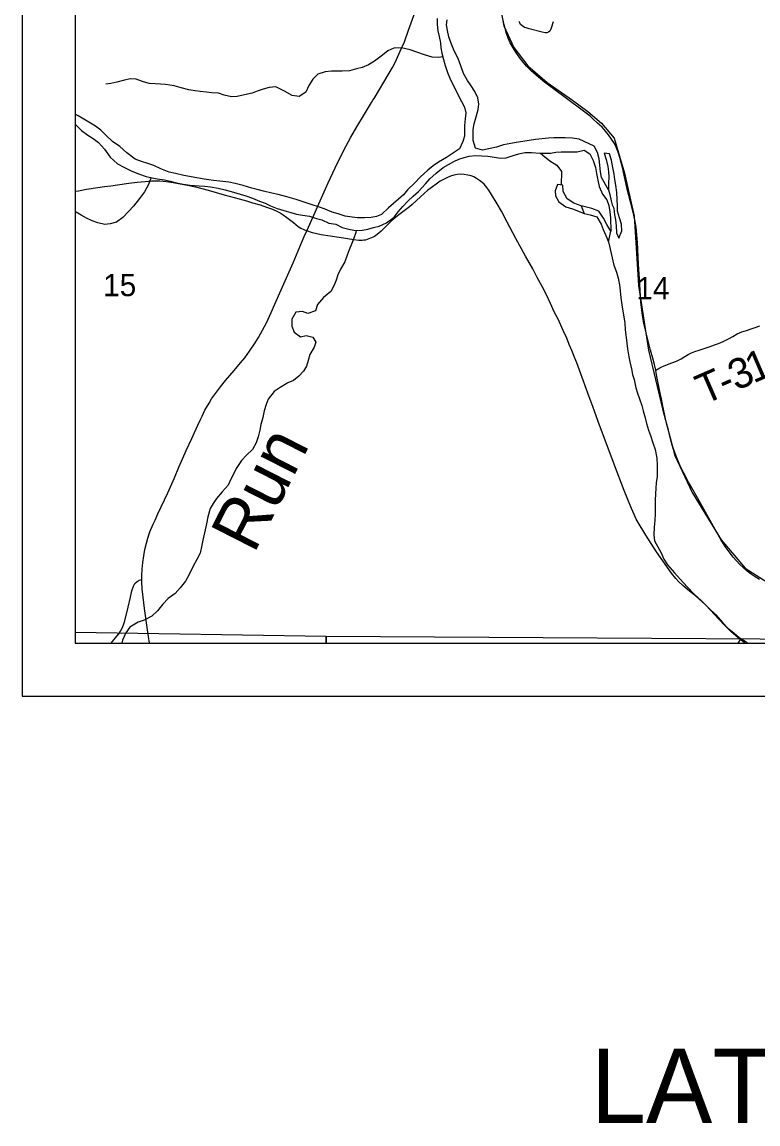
# Model space of a CAD drawing. Extents: x -7.5 to 53.5, y 0 to 22.
# Drawn here: x 2 to 3.386, y 13.194 to 15.27 of the extents above; entities that cross this region are included whole.
import ezdxf

# ---------------------------------------------------------------- set-up
doc = ezdxf.new("R2010")
doc.units = 0
for name, color, linetype in [('GM_X_Corporation', 7, 'Continuous'), ('GM_X_County_Road', 7, 'Continuous'), ('GM_X_Major_River', 7, 'Continuous'), ('GM_X_Minor_River', 7, 'Continuous'), ('GM_X_Minor_River_Text', 7, 'Continuous'), ('GM_X_Rail_Line', 7, 'Continuous'), ('GM_X_Section_Text', 7, 'Continuous'), ('GM_X_State_Route', 7, 'Continuous'), ('GM_X_Township_Road', 7, 'Continuous'), ('GM_X_Township_Road_Text', 7, 'Continuous'), ('SH_Data', 7, 'Continuous'), ('SH_Text', 7, 'Continuous')]:
    doc.layers.add(name, color=color, linetype=linetype)

msp = doc.modelspace()

# ---------------------------------------------------------------- linework, layer by layer
at = {"layer": 'GM_X_Corporation'}
msp.add_lwpolyline([(2.1, 20.9), (2.1, 14.1), (4.6151, 14.1), (4.6149, 14.11), (4.6147, 14.1199), (4.6087, 14.5302), (4.6021, 15.6139)], dxfattribs=at)
for points in [[(2.1, 14.1198), (2.1, 14.1), (2.573, 14.1), (2.573, 14.1127)], [(2.573, 14.1), (3.5941, 14.1), (3.594, 14.1064), (2.573, 14.1127)]]:
    msp.add_lwpolyline(points, close=True, dxfattribs=at)
at = {"layer": 'GM_X_County_Road'}
for points in [[(3.1934, 14.6146), (3.193, 14.6166), (3.1909, 14.6251), (3.188, 14.6371), (3.1839, 14.6522), (3.176, 14.6822), (3.1712, 14.7023), (3.1683, 14.7182), (3.1671, 14.7275), (3.1655, 14.7428), (3.1627, 14.7864), (3.161, 14.814), (3.159, 14.8549), (3.158, 14.8693), (3.1565, 14.8835), (3.154, 14.8976), (3.151, 14.9123), (3.1457, 14.9318), (3.1402, 14.9529), (3.1345, 14.9788), (3.1309, 14.9959), (3.1261, 15.0151), (3.1228, 15.0248), (3.1189, 15.0343), (3.1156, 15.0413), (3.1103, 15.0497), (3.1046, 15.0578), (3.0991, 15.0648), (3.0925, 15.072), (3.0841, 15.08), (3.0757, 15.0875), (3.0697, 15.0928), (3.06, 15.1004), (3.0228, 15.1282), (2.9842, 15.1568), (2.9724, 15.1664), (2.9595, 15.1778), (2.9502, 15.1873), (2.9435, 15.1948), (2.9368, 15.2034), (2.9297, 15.2138), (2.9252, 15.2214), (2.9196, 15.2314), (2.9156, 15.2399), (2.9125, 15.2486), (2.9096, 15.2578), (2.9078, 15.2652), (2.9062, 15.2737)], [(3.3889, 14.2198), (3.381, 14.2248), (3.3733, 14.23), (3.3658, 14.2357), (3.3587, 14.2418), (3.3518, 14.2482), (3.3453, 14.2549), (3.3392, 14.262), (3.3335, 14.2694), (3.3245, 14.2822), (3.3163, 14.2954), (3.3054, 14.3142), (3.284, 14.3521), (3.2719, 14.3738), (3.2612, 14.3927), (3.255, 14.4033), (3.2462, 14.42), (3.2395, 14.4339), (3.2342, 14.4459), (3.2299, 14.4573), (3.2247, 14.4729), (3.22, 14.4901), (3.2172, 14.5012), (3.2128, 14.5193), (3.21, 14.5322), (3.207, 14.5465), (3.2042, 14.5601), (3.2014, 14.5742), (3.1963, 14.5991), (3.1945, 14.609), (3.1934, 14.6146)], [(2.1762, 14.1097), (2.1788, 14.1128), (2.1825, 14.1176), (2.1857, 14.1228), (2.1887, 14.1282), (2.1913, 14.1344), (2.1935, 14.1417), (2.1999, 14.1679), (2.2041, 14.1864), (2.207, 14.1984), (2.2098, 14.2071), (2.2127, 14.2122), (2.2168, 14.2161), (2.2206, 14.2183), (2.2256, 14.22)], [(2.1678, 14.1), (2.173, 14.106), (2.1762, 14.1097)]]:
    msp.add_lwpolyline(points, dxfattribs=at)
at = {"layer": 'GM_X_Major_River'}
msp.add_line((3.0531, 14.9242), (3.0588, 14.9098), dxfattribs=at)
for points in [[(2.7817, 15.2772), (2.7817, 15.2655), (2.7832, 15.2537), (2.7855, 15.2431), (2.7878, 15.231), (2.7889, 15.2215), (2.7908, 15.2116), (2.7939, 15.1995), (2.7966, 15.1885), (2.8011, 15.1753), (2.8057, 15.1643), (2.8118, 15.1514), (2.8277, 15.1207), (2.8334, 15.1097), (2.8357, 15.0995), (2.8346, 15.0881), (2.8331, 15.0752), (2.8335, 15.065), (2.8331, 15.0551), (2.8304, 15.0449), (2.8236, 15.0312), (2.8127, 15.0236), (2.7994, 15.0149), (2.7842, 15.0065), (2.7744, 14.9993), (2.7642, 14.9909), (2.7498, 14.978), (2.7399, 14.967), (2.7259, 14.9541), (2.7183, 14.9446), (2.6903, 14.9203), (2.6771, 14.9078), (2.6676, 14.9036), (2.6574, 14.9017), (2.6448, 14.9013), (2.6316, 14.9016), (2.6217, 14.9024), (2.6085, 14.9043), (2.5952, 14.9088), (2.5838, 14.9122), (2.5709, 14.9179), (2.5599, 14.9216), (2.5447, 14.9265), (2.5163, 14.936), (2.4989, 14.9409), (2.4826, 14.945), (2.4704, 14.9481), (2.4545, 14.9518), (2.4427, 14.9545), (2.4329, 14.9571), (2.4166, 14.962), (2.4014, 14.9662), (2.3893, 14.9688), (2.3726, 14.9707), (2.3605, 14.9714), (2.343, 14.974), (2.3294, 14.9767), (2.3044, 14.9808), (2.2888, 14.9846), (2.2771, 14.9872), (2.2615, 14.9936), (2.2482, 14.9997), (2.2372, 15.0038), (2.2251, 15.0072)], [(3.0495, 15.0497), (3.0359, 15.0512), (3.023, 15.0523), (3.0113, 15.0523), (3.0014, 15.0519), (2.9915, 15.0512), (2.9673, 15.0489), (2.9548, 15.0473), (2.9434, 15.0454), (2.9309, 15.0431), (2.9207, 15.0416), (2.907, 15.0389), (2.8934, 15.0343), (2.8816, 15.0317), (2.8672, 15.029), (2.854, 15.0328), (2.8498, 15.0468), (2.8494, 15.0566), (2.8494, 15.0676), (2.8513, 15.0786), (2.8554, 15.0919), (2.8592, 15.1052), (2.8603, 15.1154), (2.8584, 15.1272), (2.8527, 15.1397), (2.8459, 15.1503), (2.839, 15.1601), (2.8314, 15.173), (2.8265, 15.1878), (2.8212, 15.2014), (2.814, 15.2158), (2.8075, 15.2318), (2.8041, 15.2424), (2.801, 15.2541), (2.7995, 15.2647), (2.8006, 15.2746)], [(2.2251, 15.0072), (2.213, 15.0121), (2.1974, 15.0239), (2.1841, 15.036), (2.1705, 15.0454), (2.1576, 15.0568), (2.1481, 15.0666), (2.1386, 15.0738), (2.1287, 15.0799), (2.1162, 15.0875), (2.106, 15.0935), (2.1, 15.0969)], [(2.1, 15.0777), (2.1003, 15.0776), (2.1121, 15.0658), (2.1238, 15.0568), (2.1341, 15.0511), (2.1439, 15.0431), (2.1553, 15.031), (2.166, 15.0155), (2.1796, 15.003), (2.1914, 14.9969), (2.2058, 14.9901), (2.2194, 14.9841), (2.2339, 14.9792), (2.2448, 14.9769), (2.2547, 14.9747), (2.268, 14.9728), (2.279, 14.9705), (2.2911, 14.9675), (2.3032, 14.9649), (2.3169, 14.9626), (2.3336, 14.9615), (2.3442, 14.9608), (2.3552, 14.9596), (2.3692, 14.957), (2.3825, 14.954), (2.398, 14.9495), (2.4109, 14.9461), (2.4212, 14.9427), (2.434, 14.9381), (2.4473, 14.9325), (2.4579, 14.9287), (2.4682, 14.9238), (2.4803, 14.9189), (2.4928, 14.9151), (2.5061, 14.9113), (2.5171, 14.9083), (2.5285, 14.9064), (2.5414, 14.9042), (2.5546, 14.9), (2.5645, 14.8978), (2.5781, 14.8913), (2.591, 14.8891), (2.6032, 14.8834), (2.6153, 14.88), (2.6282, 14.8774), (2.6411, 14.8778), (2.6513, 14.8797), (2.6619, 14.8831), (2.6729, 14.8858), (2.6866, 14.8922), (2.7006, 14.9025), (2.7081, 14.9128), (2.7172, 14.923), (2.7263, 14.9329), (2.7365, 14.9424), (2.7464, 14.9511), (2.76, 14.9651), (2.7683, 14.975), (2.7801, 14.9853), (2.7933, 14.9963), (2.8032, 15.002), (2.813, 15.0073), (2.8225, 15.0122), (2.8327, 15.0153), (2.8422, 15.0176), (2.854, 15.0191), (2.8661, 15.0184), (2.8771, 15.0173), (2.8896, 15.0154), (2.9014, 15.0139), (2.9116, 15.0143), (2.9249, 15.0185), (2.9355, 15.0219), (2.9472, 15.0242), (2.9597, 15.0246), (2.9753, 15.0235), (2.9855, 15.0231), (2.995, 15.0235), (3.0052, 15.025), (3.0151, 15.0254), (3.0454, 15.0255), (3.0587, 15.0289)], [(3.1044, 14.954), (3.0916, 14.9776), (3.0896, 14.9882), (3.088, 15.0007), (3.0867, 15.0124), (3.0839, 15.0242), (3.0778, 15.0363), (3.0495, 15.0497)], [(3.0587, 15.0289), (3.0696, 15.0218), (3.0757, 15.0093), (3.08, 14.9964), (3.082, 14.9847), (3.0844, 14.9722), (3.0872, 14.9601), (3.093, 14.9461), (3.1014, 14.9352), (3.1053, 14.9246), (3.1071, 14.9127), (3.1083, 14.9016), (3.1088, 14.8761)], [(3.1237, 14.8629), (3.1296, 14.8766), (3.1288, 14.8891), (3.1252, 14.9016), (3.1217, 14.9137), (3.1213, 14.924), (3.1208, 14.9357), (3.1203, 14.949), (3.1183, 14.9626), (3.1163, 14.9733), (3.115, 14.9835), (3.1126, 14.996), (3.1099, 15.01), (3.1063, 15.0221), (3.0965, 15.0232), (3.1004, 15.0114), (3.1031, 14.9978), (3.1048, 14.9879), (3.1052, 14.9785), (3.1046, 14.9663), (3.1044, 14.954)], [(3.1044, 14.954), (3.1071, 14.9452), (3.1098, 14.9332), (3.1117, 14.9259), (3.1144, 14.9197), (3.116, 14.907), (3.1175, 14.8973), (3.1187, 14.8861), (3.1198, 14.873), (3.1237, 14.8629)], [(3.1088, 14.8761), (3.1011, 14.8889), (3.0949, 14.901), (3.0861, 14.9142), (3.0731, 14.919), (3.0531, 14.9242)], [(3.0588, 14.9098), (3.0698, 14.9072), (3.0824, 14.9031), (3.0905, 14.8895), (3.0944, 14.8793), (3.0994, 14.868), (3.1048, 14.8559)], [(3.1048, 14.8559), (3.1088, 14.8761)], [(3.1048, 14.8559), (3.1147, 14.8124), (3.1193, 14.7991), (3.1225, 14.7878), (3.1252, 14.7749), (3.1265, 14.7635), (3.1277, 14.7506), (3.1294, 14.7374), (3.1314, 14.7256), (3.1334, 14.7146), (3.135, 14.7029), (3.1362, 14.69), (3.1375, 14.6756), (3.14, 14.6544), (3.1428, 14.6396), (3.1448, 14.6298), (3.1479, 14.6169), (3.1499, 14.6063), (3.1526, 14.5964), (3.1558, 14.5813), (3.1593, 14.5707), (3.1632, 14.5601), (3.1675, 14.548), (3.1698, 14.5378), (3.1734, 14.5242), (3.1761, 14.5139), (3.18, 14.5015), (3.1835, 14.4912), (3.1878, 14.4776), (3.1921, 14.4648), (3.1953, 14.4485), (3.1962, 14.4345), (3.1963, 14.4242), (3.196, 14.414), (3.1942, 14.4022), (3.1935, 14.3919), (3.1929, 14.3813), (3.1926, 14.3692), (3.1923, 14.3574), (3.1924, 14.3437), (3.1918, 14.3312), (3.1908, 14.3183), (3.1902, 14.3039), (3.1914, 14.2929), (3.1976, 14.2816), (3.2037, 14.2699), (3.2088, 14.2581), (3.2157, 14.2472), (3.2291, 14.2321), (3.2394, 14.2205), (3.2528, 14.2058), (3.2659, 14.1923), (3.2789, 14.1802), (3.293, 14.1667), (3.306, 14.1536), (3.3198, 14.1381), (3.3294, 14.128), (3.3405, 14.1193), (3.3508, 14.1103), (3.3641, 14.1021), (3.3671, 14.1)]]:
    msp.add_lwpolyline(points, dxfattribs=at)
at = {"layer": 'GM_X_Minor_River'}
msp.add_line((3.3538, 14.1085), (3.3478, 14.1), dxfattribs=at)
for points in [[(2.7926, 15.2046), (2.7852, 15.2033), (2.7723, 15.2044), (2.7579, 15.2086), (2.7435, 15.2138), (2.7309, 15.218), (2.7146, 15.2218), (2.6999, 15.221), (2.6889, 15.216), (2.6786, 15.2077), (2.6639, 15.1963), (2.6525, 15.1898), (2.6404, 15.1845), (2.6301, 15.1818), (2.6165, 15.1784), (2.6032, 15.178), (2.5828, 15.178), (2.571, 15.1764), (2.557, 15.1719), (2.5475, 15.1624), (2.54, 15.1506), (2.5343, 15.1381), (2.5218, 15.1301), (2.5085, 15.1316), (2.4941, 15.1403), (2.4782, 15.1479), (2.4657, 15.1467), (2.4539, 15.1437), (2.4429, 15.1399), (2.4335, 15.1361), (2.4191, 15.133), (2.405, 15.13), (2.3944, 15.1296), (2.3804, 15.1326), (2.3698, 15.136), (2.3569, 15.1371), (2.3474, 15.1382), (2.3353, 15.1397), (2.3258, 15.1405), (2.314, 15.1423), (2.2996, 15.1465), (2.2867, 15.1503), (2.2704, 15.1525), (2.2606, 15.1533), (2.2507, 15.1536), (2.2394, 15.1547), (2.2268, 15.1581), (2.2151, 15.1627), (2.2037, 15.163), (2.1931, 15.1607), (2.1783, 15.1569), (2.1673, 15.1546), (2.1575, 15.1531)], [(2.9764, 15.0234), (2.981, 15.0197), (2.9942, 15.0087), (3.0075, 15.0008), (3.0158, 14.9887), (3.0154, 14.9636)], [(2.2432, 14.9773), (2.2377, 14.9629), (2.2309, 14.9504), (2.221, 14.9375), (2.2097, 14.9234), (2.2013, 14.9139), (2.19, 14.9022), (2.1782, 14.8934), (2.1661, 14.89), (2.1559, 14.8888), (2.1426, 14.8919), (2.132, 14.8956), (2.1214, 14.9009), (2.1115, 14.9066), (2.102, 14.9123), (2.1, 14.9131)], [(3.0531, 14.9242), (3.0391, 14.9288), (3.0269, 14.9371), (3.0189, 14.9511), (3.0185, 14.9632), (3.0083, 14.9644), (3.0042, 14.9522), (3.0045, 14.9427), (3.011, 14.9314), (3.0239, 14.9219), (3.0368, 14.9185), (3.0482, 14.914), (3.0588, 14.9098)], [(2.6293, 14.8774), (2.6286, 14.874), (2.624, 14.8611), (2.6206, 14.8516), (2.6161, 14.8413), (2.6123, 14.8307), (2.6078, 14.8186), (2.5995, 14.8049), (2.5945, 14.7939), (2.5915, 14.7841), (2.5877, 14.7746), (2.5817, 14.7628), (2.5677, 14.751), (2.5563, 14.7381), (2.5529, 14.7264), (2.5385, 14.721), (2.5283, 14.7248), (2.5154, 14.7237), (2.5082, 14.7104), (2.5078, 14.6971), (2.5128, 14.6861), (2.5245, 14.677), (2.5348, 14.6797), (2.5477, 14.6767), (2.553, 14.6668), (2.55, 14.6574), (2.542, 14.6437), (2.539, 14.6323), (2.5356, 14.6221), (2.5303, 14.6126), (2.5216, 14.6027), (2.511, 14.5951), (2.5008, 14.5906), (2.486, 14.5814), (2.475, 14.5738), (2.4633, 14.5598), (2.4595, 14.5496), (2.4561, 14.5374), (2.4538, 14.5249), (2.45, 14.5116), (2.4478, 14.5014), (2.4444, 14.4885), (2.441, 14.4775), (2.4342, 14.465), (2.4228, 14.4543), (2.4133, 14.4441), (2.4031, 14.4293), (2.3982, 14.4183), (2.3929, 14.4077), (2.388, 14.3974), (2.377, 14.3853), (2.3664, 14.3727), (2.36, 14.3629), (2.3543, 14.3534), (2.3501, 14.3378), (2.3471, 14.3246), (2.3449, 14.3132), (2.3403, 14.2942), (2.3385, 14.2844), (2.3354, 14.2696), (2.329, 14.2578), (2.3222, 14.2449), (2.3146, 14.2294), (2.3078, 14.2168), (2.298, 14.2043), (2.2881, 14.1933), (2.2753, 14.1842), (2.265, 14.1736), (2.2548, 14.161), (2.2442, 14.1508), (2.2302, 14.1435), (2.2188, 14.1397), (2.2033, 14.1302), (2.1957, 14.1196), (2.1893, 14.1056), (2.1878, 14.1)]]:
    msp.add_lwpolyline(points, dxfattribs=at)
at = {"layer": 'GM_X_Rail_Line'}
msp.add_lwpolyline([(2.8997, 15.3022), (2.9073, 15.2631), (2.9262, 15.2226), (2.9525, 15.1876), (2.9893, 15.1564), (3.0367, 15.1232), (3.0655, 15.1017), (3.0915, 15.0796), (3.1152, 15.0515), (3.1349, 14.9857), (3.1526, 14.9047), (3.1607, 14.774), (3.1799, 14.6519), (3.2063, 14.5417), (3.2295, 14.4534), (3.2622, 14.3837), (3.3168, 14.2949), (3.3618, 14.2413), (3.41, 14.2105)], dxfattribs=at)
at = {"layer": 'GM_X_State_Route'}
for points in [[(2.5363, 14.8769), (2.5394, 14.8838), (2.5763, 14.9672), (2.5895, 14.9954), (2.6005, 15.0178), (2.6105, 15.0372), (2.6195, 15.0536), (2.6303, 15.0725), (2.6447, 15.0966), (2.6582, 15.1188), (2.6609, 15.1232), (2.6629, 15.1265), (2.6913, 15.1738), (2.6975, 15.1846), (2.7033, 15.1955), (2.7073, 15.2038), (2.7124, 15.2151), (2.7201, 15.2332), (2.728, 15.2552), (2.7379, 15.2828), (2.7477, 15.3118), (2.7591, 15.3458)], [(2.1, 14.9513), (2.1063, 14.9525), (2.1215, 14.9551), (2.1429, 14.9583), (2.1552, 14.9601), (2.1675, 14.9619), (2.1798, 14.9637), (2.2013, 14.9665), (2.2166, 14.9683), (2.232, 14.9699), (2.2381, 14.9704), (2.2441, 14.9708), (2.2502, 14.9711), (2.2594, 14.9709), (2.2717, 14.9699), (2.2848, 14.9682), (2.2975, 14.9657), (2.3113, 14.963), (2.3267, 14.9598), (2.3503, 14.9535), (2.3806, 14.9449), (2.4091, 14.9372), (2.4227, 14.9332)], [(2.4227, 14.9332), (2.4343, 14.9298), (2.4483, 14.9257), (2.4607, 14.9217), (2.4719, 14.9174), (2.4808, 14.9134), (2.4862, 14.9105), (2.4915, 14.9072), (2.499, 14.9019), (2.5112, 14.8923), (2.52, 14.8852), (2.5253, 14.8816), (2.5306, 14.8791), (2.5363, 14.8769)], [(2.3368, 14.5229), (2.339, 14.5276), (2.3445, 14.5387), (2.3521, 14.5523), (2.357, 14.5602), (2.3623, 14.568), (2.3735, 14.5828), (2.3833, 14.5948), (2.3996, 14.6137), (2.4117, 14.6278), (2.4195, 14.6374), (2.4285, 14.65), (2.4388, 14.6655), (2.4455, 14.676), (2.4531, 14.6894), (2.4603, 14.7032), (2.4693, 14.7229), (2.4857, 14.7599), (2.4908, 14.7712), (2.5105, 14.8168), (2.5262, 14.8541), (2.5316, 14.866), (2.5363, 14.8769)], [(2.2506, 14.3319), (2.2559, 14.3437), (2.2744, 14.383), (2.2871, 14.4114), (2.2955, 14.4314), (2.3029, 14.4485), (2.3093, 14.4627), (2.3197, 14.4853), (2.3247, 14.4966), (2.331, 14.5107), (2.3368, 14.5229)], [(2.2398, 14.1), (2.2363, 14.1249), (2.2309, 14.165), (2.228, 14.1865), (2.2264, 14.202), (2.2257, 14.2145), (2.2256, 14.22), (2.2256, 14.227), (2.2262, 14.2394), (2.2274, 14.2519), (2.2291, 14.2642), (2.2313, 14.2765), (2.2341, 14.2886), (2.2368, 14.2976), (2.2409, 14.3094), (2.2469, 14.3238), (2.2506, 14.3319)]]:
    msp.add_lwpolyline(points, dxfattribs=at)
at = {"layer": 'GM_X_Township_Road'}
for points in [[(3, 15.2708), (2.9966, 15.2588), (2.9955, 15.2559), (2.9939, 15.2533), (2.9914, 15.2514), (2.9886, 15.2502), (2.9855, 15.2501), (2.9794, 15.2513), (2.9552, 15.2573), (2.9493, 15.2591), (2.9464, 15.2603), (2.9436, 15.2617), (2.9411, 15.2635), (2.939, 15.2658), (2.9375, 15.2685), (2.9365, 15.2715)], [(3.3613, 14.1), (3.3607, 14.1004), (3.3535, 14.106), (3.3489, 14.1099), (3.3352, 14.122), (3.3241, 14.1327), (3.3114, 14.1456), (3.2969, 14.162), (3.287, 14.172), (3.2686, 14.1888), (3.2568, 14.1979), (3.2446, 14.2087), (3.2367, 14.2156), (3.2313, 14.2217), (3.2233, 14.232), (3.1946, 14.2719), (3.1749, 14.3033), (3.169, 14.3128), (3.1642, 14.3211), (3.1606, 14.3274), (3.1569, 14.3336), (3.1527, 14.3426), (3.148, 14.3536), (3.1339, 14.3873), (3.1155, 14.4351), (3.0853, 14.5176), (3.0748, 14.5461), (3.068, 14.5642), (3.0501, 14.6141), (3.0448, 14.6284), (3.0412, 14.637), (3.0353, 14.6513), (3.0306, 14.6628), (3.0279, 14.6697), (3.0247, 14.6776), (3.0219, 14.6837), (3.0097, 14.7103), (3.0024, 14.7244), (2.9951, 14.7397), (2.9875, 14.7563), (2.9794, 14.7719), (2.9702, 14.7888), (2.9621, 14.8051), (2.9479, 14.8292), (2.93, 14.8622), (2.9246, 14.8732), (2.9189, 14.8836), (2.9129, 14.8946), (2.9027, 14.9139), (2.8951, 14.9276), (2.8843, 14.9455), (2.8792, 14.9535), (2.8755, 14.9588), (2.8704, 14.9647), (2.8663, 14.9681), (2.8639, 14.97), (2.8614, 14.9719), (2.8562, 14.9753), (2.8508, 14.9784), (2.8456, 14.9804), (2.8397, 14.9818), (2.8326, 14.9832), (2.8258, 14.9836), (2.8192, 14.9828), (2.8133, 14.9818), (2.8068, 14.9797), (2.8014, 14.9772), (2.7935, 14.9736), (2.7875, 14.9703), (2.7798, 14.9648), (2.7732, 14.9598), (2.7644, 14.9532), (2.7505, 14.9411), (2.7345, 14.9262), (2.7298, 14.9221), (2.7099, 14.9072), (2.6999, 14.8995), (2.6935, 14.893), (2.6862, 14.886)], [(2.6862, 14.886), (2.6761, 14.8763), (2.6718, 14.8723), (2.6662, 14.8681), (2.6637, 14.8664), (2.6611, 14.8648), (2.6564, 14.8628), (2.6533, 14.8616), (2.65, 14.8605), (2.6468, 14.8595), (2.6438, 14.859), (2.6404, 14.8588), (2.6342, 14.8588), (2.6249, 14.8596), (2.5973, 14.8641), (2.5634, 14.8695), (2.5549, 14.8712), (2.5471, 14.8733), (2.5363, 14.8769)], [(3.1934, 14.6146), (3.2012, 14.6187), (3.2039, 14.6201), (3.2094, 14.6223), (3.2241, 14.6281), (3.2325, 14.6312), (3.2416, 14.6357), (3.2484, 14.6399), (3.2545, 14.6438), (3.2611, 14.6472), (3.2671, 14.6495), (3.2755, 14.6521), (3.2863, 14.6558), (3.296, 14.6589), (3.3043, 14.6619), (3.3116, 14.6648), (3.3203, 14.6685), (3.3303, 14.6734), (3.3387, 14.6779), (3.3468, 14.6825), (3.3558, 14.6864), (3.3647, 14.6893), (3.3735, 14.6919), (3.3809, 14.6945), (3.3893, 14.6981)]]:
    msp.add_lwpolyline(points, dxfattribs=at)
at = {"layer": 'SH_Data'}
for p, q in [((2, 21), (2, 14)), ((2.1, 20.9), (2.1, 14.1)), ((2.1, 14.1), (8.9, 14.1)), ((2, 14), (9, 14))]:
    msp.add_line(p, q, dxfattribs=at)

# ---------------------------------------------------------------- texts
at = {"layer": 'GM_X_Minor_River_Text'}
msp.add_text('Run', height=0.09472, rotation=62.9498, dxfattribs=at).set_placement((2.4367, 14.2666))
at = {"layer": 'GM_X_Section_Text'}
for s, p in [('15', (2.1528, 14.7537)), ('14', (3.157, 14.7477))]:
    msp.add_text(s, height=0.04186, rotation=0, dxfattribs=at).set_placement(p)
at = {"layer": 'GM_X_Township_Road_Text'}
for s, rotation, p in [('3', 23.4893, (3.3451, 14.575)), ('1', 23.2632, (3.3772, 14.5889)), ('T', 23.57, (3.2848, 14.5487)), ('-', 23.5543, (3.3237, 14.5657))]:
    msp.add_text(s, height=0.0568, rotation=rotation, dxfattribs=at).set_placement(p)
at = {"layer": 'SH_Text'}
msp.add_text('LATITUDE:  40°38\'40"     LONGITUDE:  82°12\'30"', height=0.14, dxfattribs=at).set_placement((3.071, 13.1959))

doc.saveas('drawing.dxf')
